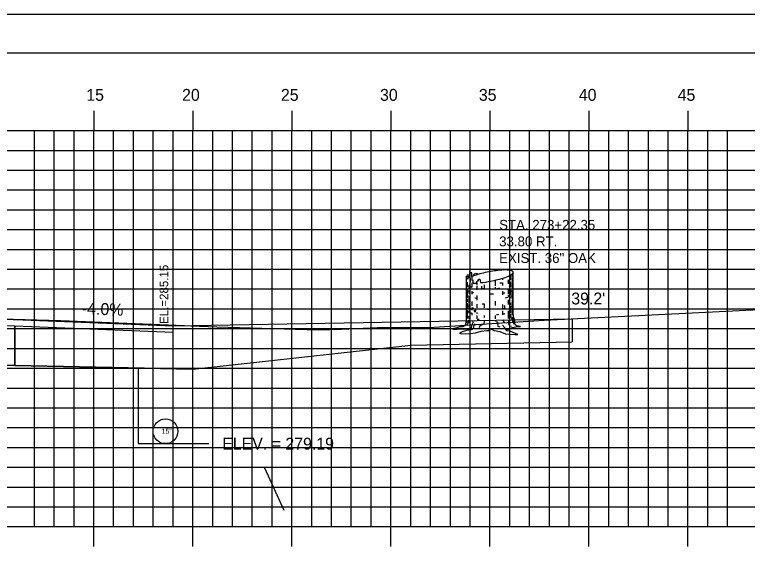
# Model space of a CAD drawing. Extents: x 852672 to 852842, y 366268 to 366378.
# Drawn here: x 852766.1 to 852803.09, y 366351.08 to 366378.18 of the extents above; entities that cross this region are included whole.
import ezdxf

# ---------------------------------------------------------------- set-up
doc = ezdxf.new("R2010")
doc.units = 0
for name, color, linetype in [('ANNOTATION', 7, 'Continuous'), ('BORDER', 7, 'Continuous'), ('D_Roadway_Drive_Gravel_RT', 7, 'Continuous'), ('D_Roadway_Drive_SubGrade', 7, 'Continuous'), ('D_Roadway_Edge_Shoulder', 7, 'Continuous'), ('D_Roadway_SubGrade', 7, 'Continuous'), ('D_Text_Monospaced', 7, 'Continuous'), ('D_Text_Standard', 7, 'Continuous'), ('H_V ANNOTATION', 7, 'Continuous'), ('JUNK COM EXC', 7, 'Continuous'), ('junk strct exc', 7, 'Continuous'), ('MAJOR', 7, 'Continuous'), ('MINOR', 7, 'Continuous'), ('PDRAIN', 7, 'Continuous'), ('PLOT BOUNDARY', 7, 'Continuous'), ('S_Roadway_Centerline', 7, 'Continuous'), ('S_Trees_Decid_Pay', 7, 'Continuous')]:
    doc.layers.add(name, color=color, linetype=linetype)

msp = doc.modelspace()

# ---------------------------------------------------------------- linework, layer by layer
at = {"layer": 'ANNOTATION'}
msp.add_line((852779.7, 366353.149), (852778.732, 366355.276), dxfattribs=at)
at = {"layer": 'BORDER'}
msp.add_line((852840.097, 366376.236), (852680.097, 366376.236), dxfattribs=at)
at = {"layer": 'D_Roadway_Drive_Gravel_RT'}
for p, q in [((852774.096, 366362.473), (852794.249, 366362.817)), ((852774.096, 366362.14), (852774.096, 366362.473)), ((852786.096, 366361.487), (852794.249, 366361.65))]:
    msp.add_line(p, q, dxfattribs=at)
at = {"layer": 'D_Roadway_Drive_SubGrade'}
for p, q in [((852794.249, 366362.817), (852794.249, 366361.65)), ((852775.086, 366360.282), (852786.096, 366361.487))]:
    msp.add_line(p, q, dxfattribs=at)
at = {"layer": 'D_Roadway_Edge_Shoulder'}
msp.add_line((852766.097, 366362.793), (852774.096, 366362.473), dxfattribs=at)
at = {"layer": 'D_Roadway_SubGrade'}
for p, q in [((852766.11, 366362.461), (852774.096, 366362.141)), ((852766.11, 366360.461), (852766.11, 366362.461)), ((852775.086, 366360.282), (852766.11, 366360.461))]:
    msp.add_line(p, q, dxfattribs=at)
msp.add_lwpolyline([(852744.11, 366360.461), (852744.11, 366362.461), (852755.11, 366362.681), (852766.11, 366362.461), (852766.11, 366360.461), (852755.11, 366360.681)], close=True, dxfattribs=at)
at = {"layer": 'D_Text_Standard'}
msp.add_lwpolyline([(852775.086, 366356.517), (852775.217, 366356.517), (852775.897, 366356.517)], dxfattribs=at)
at = {"layer": 'JUNK COM EXC'}
msp.add_lwpolyline([(852735.096, 366362.066), (852735.096, 366360.28), (852744.11, 366360.461), (852755.11, 366360.681), (852766.11, 366360.461), (852775.086, 366360.282), (852775.096, 366362.456), (852768.422, 366362.719), (852759.991, 366362.96), (852755.187, 366363.083), (852747.417, 366362.872), (852743.133, 366362.791), (852740.774, 366362.627), (852736.929, 366362.331)], close=True, dxfattribs=at)
at = {"layer": 'junk strct exc'}
msp.add_lwpolyline([(852772.336, 366360.336), (852772.336, 366356.517), (852775.086, 366356.517), (852775.086, 366360.282), (852772.336, 366360.336)], dxfattribs=at)
at = {"layer": 'MAJOR'}
for p, q in [((852770.096, 366373.329), (852770.096, 366372.327)), ((852775.096, 366373.329), (852775.096, 366372.327)), ((852780.096, 366373.329), (852780.096, 366372.327)), ((852785.096, 366373.329), (852785.096, 366372.327)), ((852790.096, 366373.329), (852790.096, 366372.327)), ((852795.096, 366373.329), (852795.096, 366372.327)), ((852800.096, 366373.329), (852800.096, 366372.327)), ((852685.096, 366372.327), (852825.096, 366372.327)), ((852685.096, 366372.327), (852825.096, 366372.327)), ((852770.096, 366352.327), (852770.096, 366372.327)), ((852775.096, 366352.327), (852775.096, 366372.327)), ((852780.096, 366352.327), (852780.096, 366372.327)), ((852785.096, 366352.327), (852785.096, 366372.327)), ((852790.096, 366352.327), (852790.096, 366372.327)), ((852795.096, 366352.327), (852795.096, 366372.327)), ((852800.096, 366352.327), (852800.096, 366372.327)), ((852685.096, 366367.327), (852825.096, 366367.327)), ((852685.096, 366362.327), (852825.096, 366362.327)), ((852685.096, 366357.327), (852825.096, 366357.327)), ((852685.096, 366352.327), (852825.096, 366352.327)), ((852685.096, 366352.327), (852825.096, 366352.327)), ((852770.096, 366351.325), (852770.096, 366352.327)), ((852775.096, 366351.325), (852775.096, 366352.327)), ((852780.096, 366351.325), (852780.096, 366352.327)), ((852785.096, 366351.325), (852785.096, 366352.327)), ((852790.096, 366351.325), (852790.096, 366352.327)), ((852795.096, 366351.325), (852795.096, 366352.327)), ((852800.096, 366351.325), (852800.096, 366352.327))]:
    msp.add_line(p, q, dxfattribs=at)
at = {"layer": 'MINOR'}
for p, q in [((852767.096, 366352.327), (852767.096, 366372.327)), ((852768.096, 366352.327), (852768.096, 366372.327)), ((852769.096, 366352.327), (852769.096, 366372.327)), ((852771.096, 366352.327), (852771.096, 366372.327)), ((852772.096, 366352.327), (852772.096, 366372.327)), ((852773.096, 366352.327), (852773.096, 366372.327)), ((852774.096, 366352.327), (852774.096, 366372.327)), ((852776.096, 366352.327), (852776.096, 366372.327)), ((852777.096, 366352.327), (852777.096, 366372.327)), ((852778.096, 366352.327), (852778.096, 366372.327)), ((852779.096, 366352.327), (852779.096, 366372.327)), ((852781.096, 366352.327), (852781.096, 366372.327)), ((852782.096, 366352.327), (852782.096, 366372.327)), ((852783.096, 366352.327), (852783.096, 366372.327)), ((852784.096, 366352.327), (852784.096, 366372.327)), ((852786.096, 366352.327), (852786.096, 366372.327)), ((852787.096, 366352.327), (852787.096, 366372.327)), ((852788.096, 366352.327), (852788.096, 366372.327)), ((852789.096, 366352.327), (852789.096, 366372.327)), ((852791.096, 366352.327), (852791.096, 366372.327)), ((852792.096, 366352.327), (852792.096, 366372.327)), ((852793.096, 366352.327), (852793.096, 366372.327)), ((852794.096, 366352.327), (852794.096, 366372.327)), ((852796.096, 366352.327), (852796.096, 366372.327)), ((852797.096, 366352.327), (852797.096, 366372.327)), ((852798.096, 366352.327), (852798.096, 366372.327)), ((852799.096, 366352.327), (852799.096, 366372.327)), ((852801.096, 366352.327), (852801.096, 366372.327)), ((852802.096, 366352.327), (852802.096, 366372.327)), ((852685.096, 366371.327), (852825.096, 366371.327)), ((852685.096, 366370.327), (852825.096, 366370.327)), ((852685.096, 366369.327), (852825.096, 366369.327)), ((852685.096, 366368.327), (852825.096, 366368.327)), ((852685.096, 366366.327), (852825.096, 366366.327)), ((852685.096, 366365.327), (852825.096, 366365.327)), ((852685.096, 366364.327), (852825.096, 366364.327)), ((852685.096, 366363.327), (852825.096, 366363.327)), ((852685.096, 366361.327), (852825.096, 366361.327)), ((852685.096, 366360.327), (852825.096, 366360.327)), ((852685.096, 366359.327), (852825.096, 366359.327)), ((852685.096, 366358.327), (852825.096, 366358.327)), ((852685.096, 366356.327), (852825.096, 366356.327)), ((852685.096, 366355.327), (852825.096, 366355.327)), ((852685.096, 366354.327), (852825.096, 366354.327)), ((852685.096, 366353.327), (852825.096, 366353.327))]:
    msp.add_line(p, q, dxfattribs=at)
at = {"layer": 'PDRAIN'}
msp.add_lwpolyline([(852772.336, 366360.336), (852772.336, 366356.517), (852775.086, 366356.517), (852775.086, 366360.282)], dxfattribs=at)
msp.add_circle((852773.711, 366357.142), 0.625, dxfattribs=at)
at = {"layer": 'PLOT BOUNDARY'}
msp.add_lwpolyline([(852672.003, 366268.177), (852842.003, 366268.177), (852842.003, 366378.177), (852672.003, 366378.177)], close=True, dxfattribs=at)
at = {"layer": 'S_Roadway_Centerline'}
msp.add_lwpolyline([(852706.614, 366362.002), (852711.434, 366361.992), (852721.194, 366361.85), (852723.222, 366361.85), (852731.301, 366362.174), (852731.997, 366362.154), (852734.142, 366361.931), (852735.024, 366362.055), (852736.929, 366362.331), (852740.774, 366362.627), (852743.133, 366362.791), (852747.417, 366362.872), (852755.187, 366363.083), (852759.991, 366362.96), (852768.422, 366362.719), (852776.31, 366362.408), (852781.428, 366362.26), (852782.594, 366362.294), (852784.415, 366362.377), (852787.287, 366362.402), (852792.84, 366362.746), (852804.042, 366363.313), (852809.881, 366363.563), (852812.01, 366363.649)], dxfattribs=at)
at = {"layer": 'S_Trees_Decid_Pay'}
for p, q in [((852791.14, 366365.037), (852791.14, 366364.784)), ((852791.22, 366365.082), (852791.22, 366364.961)), ((852788.946, 366364.679), (852788.946, 366364.424)), ((852789.096, 366364.879), (852789.096, 366364.704)), ((852790.352, 366364.77), (852790.352, 366364.49)), ((852790.736, 366364.871), (852790.736, 366364.784)), ((852791.008, 366364.784), (852791.008, 366364.593)), ((852791.14, 366364.688), (852791.14, 366364.424)), ((852791.22, 366364.91), (852791.22, 366364.696)), ((852788.946, 366364.327), (852788.946, 366363.858)), ((852789.032, 366364.533), (852789.032, 366364.321)), ((852789.18, 366364.63), (852789.18, 366364.425)), ((852789.442, 366364.632), (852789.442, 366364.513)), ((852789.442, 366364.461), (852789.442, 366364.276)), ((852789.68, 366364.36), (852789.685, 366364.467)), ((852789.806, 366364.533), (852789.806, 366364.353)), ((852790.352, 366364.424), (852790.352, 366364.321)), ((852790.736, 366364.643), (852790.736, 366364.504)), ((852791.008, 366364.341), (852791.008, 366364.064)), ((852791.14, 366364.327), (852791.14, 366364.018)), ((852791.22, 366364.65), (852791.22, 366364.312)), ((852789.032, 366364.255), (852789.032, 366364.107)), ((852789.032, 366363.93), (852789.032, 366363.629)), ((852789.18, 366364.218), (852789.18, 366364.064)), ((852789.442, 366363.99), (852789.442, 366363.761)), ((852790.736, 366364.218), (852790.736, 366364.026)), ((852791.008, 366364.018), (852791.008, 366363.91)), ((852791.14, 366363.93), (852791.14, 366363.864)), ((852791.22, 366364.196), (852791.22, 366363.835)), ((852788.946, 366363.806), (852788.946, 366363.673)), ((852788.946, 366363.615), (852788.946, 366363.289)), ((852789.032, 366363.592), (852789.032, 366363.349)), ((852789.18, 366363.701), (852789.18, 366363.481)), ((852789.442, 366363.563), (852789.442, 366363.378)), ((852789.806, 366363.575), (852789.806, 366363.378)), ((852790.352, 366363.709), (852790.352, 366363.489)), ((852790.736, 366363.547), (852790.736, 366363.339)), ((852791.008, 366363.775), (852791.008, 366363.547)), ((852791.14, 366363.629), (852791.14, 366363.532)), ((852791.22, 366363.798), (852791.22, 366363.349)), ((852788.946, 366363.261), (852788.946, 366362.841)), ((852789.032, 366363.238), (852789.032, 366363.098)), ((852789.18, 366363.381), (852789.18, 366363.261)), ((852790.736, 366363.217), (852790.736, 366363.018)), ((852791.008, 366363.217), (852791.008, 366362.834)), ((852791.14, 366363.481), (852791.14, 366363.121)), ((852791.22, 366363.284), (852791.22, 366363.001)), ((852789.032, 366362.966), (852789.032, 366362.81)), ((852789.18, 366363.11), (852789.18, 366363.011)), ((852789.442, 366363.143), (852789.442, 366363.066)), ((852789.442, 366362.989), (852789.442, 366362.816)), ((852789.806, 366362.995), (852789.806, 366362.892)), ((852790.352, 366362.989), (852790.352, 366362.816)), ((852791.14, 366363.069), (852791.14, 366362.902)), ((852788.95, 366362.738), (852788.935, 366362.62)), ((852790.731, 366362.761), (852790.811, 366362.629))]:
    msp.add_line(p, q, dxfattribs=at)
for points in [[(852788.896, 366364.953), (852788.896, 366362.816), (852788.875, 366362.674), (852788.869, 366362.548), (852788.826, 366362.461), (852788.734, 366362.412), (852788.598, 366362.412), (852788.354, 366362.356), (852788.188, 366362.307), (852788.33, 366362.276), (852788.567, 366362.314), (852788.777, 366362.301), (852789.038, 366362.307), (852789.162, 366362.326), (852789.192, 366362.283), (852789.255, 366362.326), (852789.156, 366362.258), (852788.921, 366362.233), (852788.69, 366362.171), (852788.56, 366362.101), (852788.659, 366362.058), (852789.081, 366362.077), (852789.36, 366362.12), (852789.658, 366362.196), (852789.944, 366362.233), (852790.049, 366362.233), (852790.068, 366362.314), (852790.136, 366362.32), (852790.303, 366362.233), (852790.589, 366362.177), (852790.887, 366362.07), (852791.346, 366362.021), (852791.501, 366362.034), (852791.159, 366362.184), (852790.955, 366362.215), (852790.967, 366362.289), (852791.227, 366362.388), (852791.402, 366362.419), (852791.643, 366362.431), (852791.445, 366362.468), (852791.383, 366362.505), (852791.359, 366362.591), (852791.346, 366362.761), (852791.301, 366362.847), (852791.273, 366363.087), (852791.273, 366365.173)], [(852789.252, 366364.625), (852789.244, 366364.77), (852789.199, 366364.762), (852789.184, 366365.137), (852789.09, 366365.144), (852789.075, 366365.224), (852789.038, 366364.887), (852788.993, 366364.982), (852788.972, 366364.827), (852788.896, 366364.953), (852788.902, 366364.763)], [(852788.896, 366364.953), (852788.942, 366364.976), (852788.964, 366365.041), (852789.016, 366365.064), (852789.049, 366364.99)], [(852789.274, 366364.992), (852789.295, 366365.099), (852789.427, 366365.13), (852789.434, 366365.042)], [(852789.413, 366364.63), (852789.45, 366364.733), (852789.516, 366364.739), (852789.516, 366364.821), (852789.59, 366364.827), (852789.615, 366364.647)], [(852789.304, 366363.261), (852789.295, 366363.186), (852789.369, 366363.181), (852789.384, 366363.297)], [(852790.849, 366363.352), (852790.848, 366363.429), (852790.84, 366363.495)], [(852791.165, 366362.848), (852791.237, 366362.745), (852791.237, 366362.62)], [(852791.222, 366362.929), (852791.283, 366362.768), (852791.297, 366362.643), (852791.289, 366362.546)], [(852789.016, 366362.745), (852789.009, 366362.62), (852788.927, 366362.526)], [(852789.162, 366362.326), (852789.18, 366362.505), (852789.242, 366362.641), (852789.236, 366362.742)], [(852789.353, 366362.573), (852789.279, 366362.505), (852789.261, 366362.406), (852789.255, 366362.326)], [(852789.804, 366362.709), (852789.787, 366362.555), (852789.59, 366362.474), (852789.545, 366362.371)], [(852790.37, 366362.7), (852790.473, 366362.649), (852790.488, 366362.443), (852790.591, 366362.414)], [(852790.955, 366362.215), (852790.869, 366362.356), (852790.737, 366362.499)], [(852791.025, 366362.774), (852791.025, 366362.569), (852791.083, 366362.459), (852791.18, 366362.443)]]:
    msp.add_lwpolyline(points, dxfattribs=at)
for centre, radius, start, end in [((852791.186, 366359.172), 6.126, 100.7779, 107.8613), ((852791.186, 366359.172), 6.126, 93.6944, 100.7779), ((852790.875, 366363.988), 1.299, 78.2779, 93.6944), ((852790.464, 366366.147), 1.299, 287.8613, 303.2779), ((852791.041, 366364.791), 0.48, 69.9843, 78.2779), ((852790.914, 366365.461), 0.48, 303.2779, 311.5714), ((852791.149, 366365.087), 0.164, 55.7779, 69.9843), ((852791.123, 366365.225), 0.164, 311.5714, 325.7779), ((852791.181, 366365.134), 0.107, 45.9547, 55.7779), ((852791.211, 366365.165), 0.0645, 33.2779, 45.9547), ((852791.17, 366365.193), 0.107, 325.7779, 335.6011), ((852791.219, 366365.171), 0.0544, 22.46, 33.2779), ((852791.209, 366365.176), 0.0645, 335.6011, 348.2779), ((852791.226, 366365.173), 0.0467, 10.7779, 22.46), ((852791.226, 366365.173), 0.0467, 359.0957, 10.7779), ((852791.219, 366365.174), 0.0544, 348.2779, 359.0957), ((852789.705, 366363.766), 1.299, 107.8613, 113.3069), ((852788.983, 366370.74), 6.126, 275.9147, 280.7779), ((852788.983, 366370.74), 6.126, 280.7779, 287.8613), ((852790.661, 366365.936), 1.292, 285.5651, 289.0916), ((852791.133, 366364.916), 0.166, 301.67, 315), ((852791.174, 366364.876), 0.109, 315, 324.8263), ((852791.209, 366364.851), 0.0657, 324.8263, 337.5), ((852791.219, 366364.847), 0.0554, 337.5, 348.3185), ((852788.944, 366364.584), 0.0476, 180, 191.6815), ((852788.951, 366364.586), 0.0554, 191.6815, 202.5), ((852788.961, 366364.59), 0.0657, 202.5, 215.1737), ((852788.996, 366364.615), 0.109, 215.1737, 225), ((852789.037, 366364.656), 0.166, 225, 239.1924), ((852789.509, 366365.675), 1.292, 250.6119, 255.2856), ((852789.294, 366365.924), 1.299, 268.1289, 273.6944), ((852788.983, 366370.74), 6.126, 273.6944, 274.0246), ((852790.085, 366370.263), 5.916, 266.0776, 267.3043), ((852790.085, 366370.263), 5.916, 273.5382, 274.8924), ((852790.086, 366370.524), 5.916, 274.9515, 276.3087), ((852790.66, 366365.675), 1.292, 288.0829, 292.5), ((852790.97, 366364.929), 0.484, 297.4162, 300.8076), ((852791.132, 366364.656), 0.166, 300.8076, 315), ((852791.173, 366364.615), 0.109, 315, 324.8263), ((852791.208, 366364.59), 0.0657, 324.8263, 337.5), ((852791.218, 366364.586), 0.0554, 337.5, 348.3185), ((852788.944, 366364.064), 0.0476, 180, 191.6815), ((852788.951, 366364.065), 0.0554, 191.6815, 202.5), ((852788.961, 366364.069), 0.0657, 202.5, 215.1737), ((852788.996, 366364.094), 0.109, 215.1737, 225), ((852789.037, 366364.135), 0.166, 225, 239.1924), ((852789.037, 366364.392), 0.166, 237.0378, 239.1924), ((852789.2, 366364.665), 0.484, 239.1924, 247.5), ((852789.2, 366364.408), 0.484, 239.1924, 245.7725), ((852789.509, 366365.411), 1.292, 247.5, 248.3537), ((852789.509, 366365.154), 1.292, 247.5, 248.4842), ((852789.509, 366365.411), 1.292, 255.2856, 259.2632), ((852790.085, 366369.999), 5.916, 270.1162, 271.7708), ((852790.085, 366369.999), 5.916, 276.3184, 277.1546), ((852790.66, 366365.411), 1.292, 277.1546, 278.3662), ((852790.66, 366365.411), 1.292, 291.8071, 292.5), ((852790.97, 366364.665), 0.484, 292.5, 300.8076), ((852790.97, 366364.408), 0.484, 294.6372, 300.8076), ((852791.132, 366364.392), 0.166, 300.8076, 301.6001), ((852791.132, 366364.135), 0.166, 300.8076, 315), ((852791.173, 366364.094), 0.109, 315, 324.8263), ((852791.208, 366364.069), 0.0657, 324.8263, 337.5), ((852791.218, 366364.065), 0.0554, 337.5, 348.3185), ((852788.944, 366363.806), 0.0476, 180, 191.6815), ((852788.951, 366363.808), 0.0554, 191.6815, 202.5), ((852788.961, 366363.812), 0.0657, 202.5, 215.1737), ((852788.996, 366363.837), 0.109, 215.1737, 225), ((852789.037, 366363.877), 0.166, 225, 239.1924), ((852789.509, 366364.897), 1.292, 247.5, 251.799), ((852789.509, 366365.154), 1.292, 261.8726, 262.8454), ((852790.085, 366369.742), 5.916, 262.8454, 263.7595), ((852790.085, 366369.484), 5.916, 266.2721, 267.3043), ((852790.66, 366365.154), 1.292, 279.2565, 285.6105), ((852790.66, 366364.897), 1.292, 285.6105, 290.1001), ((852791.132, 366363.877), 0.166, 302.0694, 315), ((852791.173, 366363.837), 0.109, 315, 324.8263), ((852791.208, 366363.812), 0.0657, 324.8263, 337.5), ((852791.218, 366363.808), 0.0554, 337.5, 348.3185), ((852788.944, 366363.541), 0.0476, 180, 191.6815), ((852788.951, 366363.542), 0.0554, 191.6815, 202.5), ((852788.961, 366363.546), 0.0657, 202.5, 215.1737), ((852788.996, 366363.571), 0.109, 215.1737, 225), ((852789.037, 366363.612), 0.166, 225, 239.1924), ((852789.2, 366363.885), 0.484, 239.1924, 247.5), ((852789.2, 366363.613), 0.484, 242.734, 247.5), ((852789.509, 366364.631), 1.292, 247.5, 248.3537), ((852789.509, 366364.631), 1.292, 255.2856, 259.2463), ((852790.085, 366369.219), 5.916, 268.9207, 270), ((852790.085, 366369.219), 5.916, 270, 270.2757), ((852790.085, 366369.219), 5.916, 276.3184, 277.1546), ((852790.66, 366364.631), 1.292, 277.1546, 278.3795), ((852790.97, 366363.885), 0.484, 292.5, 300.8076), ((852791.132, 366363.612), 0.166, 300.8076, 302.0694), ((852791.132, 366363.34), 0.166, 302.0694, 315), ((852791.173, 366363.299), 0.109, 315, 324.8263), ((852791.208, 366363.274), 0.0657, 324.8263, 337.5), ((852791.218, 366363.542), 0.0554, 337.5, 348.3185), ((852791.218, 366363.27), 0.0554, 337.5, 348.3185), ((852788.944, 366363.011), 0.0476, 180, 191.6815), ((852788.951, 366363.013), 0.0554, 191.6815, 202.5), ((852788.961, 366363.017), 0.0657, 202.5, 215.1737), ((852788.996, 366363.042), 0.109, 215.1737, 225), ((852789.037, 366363.083), 0.166, 225, 239.1924), ((852789.2, 366363.355), 0.484, 239.1924, 247.5), ((852789.509, 366364.102), 1.292, 247.5, 248.3537), ((852789.509, 366364.359), 1.292, 251.3664, 255.2856), ((852790.085, 366368.69), 5.916, 263.7831, 264.7656), ((852790.085, 366368.947), 5.916, 273.2637, 274.461), ((852790.085, 366368.947), 5.916, 276.3184, 277.1546), ((852790.66, 366364.359), 1.292, 277.1546, 278.3662), ((852790.66, 366364.359), 1.292, 285.6105, 289.1534), ((852790.67, 366364.106), 1.292, 291.3696, 292.0604), ((852790.97, 366363.355), 0.484, 292.5, 296.5499)]:
    msp.add_arc(centre, radius, start, end, dxfattribs=at)

# ---------------------------------------------------------------- texts
at = {"layer": 'ANNOTATION'}
msp.add_text('-4.0%', height=0.6, rotation=357.7097, dxfattribs=at).set_placement((852769.482, 366363.058))
at = {"layer": 'D_Text_Monospaced'}
for s, height, p in [('STA. 273+22.35', 0.49998, (852790.562, 366367.314)), ('33.80 RT.', 0.5, (852790.562, 366366.48)), ('EXIST. 36" OAK', 0.49998, (852790.562, 366365.64))]:
    msp.add_text(s, height=height, dxfattribs=at).set_placement(p)
at = {"layer": 'D_Text_Standard'}
msp.add_text(' EL.=285.15', height=0.4335, rotation=90, dxfattribs=at).set_placement((852773.851, 366362.404))
for s, p in [("39.2'", (852794.203, 366363.546)), ('ELEV. = 279.19', (852776.577, 366356.217))]:
    msp.add_text(s, height=0.6, dxfattribs=at).set_placement(p)
at = {"layer": 'H_V ANNOTATION'}
for s, p in [('15', (852769.714, 366373.827)), ('20', (852774.55, 366373.827)), ('25', (852779.542, 366373.827)), ('30', (852784.545, 366373.827)), ('35', (852789.537, 366373.827)), ('40', (852794.583, 366373.827)), ('45', (852799.575, 366373.827))]:
    msp.add_text(s, height=0.6, dxfattribs=at).set_placement(p)
at = {"layer": 'PDRAIN'}
msp.add_text('15"', height=0.25, dxfattribs=at).set_placement((852773.524, 366357.017))

doc.saveas('drawing.dxf')
